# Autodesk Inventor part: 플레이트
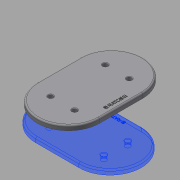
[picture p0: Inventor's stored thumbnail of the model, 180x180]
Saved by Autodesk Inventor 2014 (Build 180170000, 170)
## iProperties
Created: 2016-08
Part Number: 플레이트
Material: 알루미늄 6061
Document SubType Name: Modeling
Designer: mduedu
Density: 2.71 g/cm^3
Appearance: 기본값
Mass: 665.118 g
Surface Area: 557.689 cm^2
Volume: 245.431 cm^3
Author: mduedu
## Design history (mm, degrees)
sketch "스케치1" dims "d0" = 220, "d2" = 130
  geometry: L1 (45, 65)-(-45, 65); L2 (-45, 65)-(-45, -65); L3 (-45, -65)-(45, -65); L4 (45, -65)-(45, 65); L5 (45, 65)-(-45, -65); L6 (-45, 65)-(45, -65); 5 further points
  constraints: 12 end point, 5 midpoint, 2 parallel, 2 vertical alignment, 1 coincident, 1 horizontal, 1 perpendicular, 4 other
extrude "돌출1" new body sketch "스케치1" distance "d3" = 10; taper "d4" = 0 deg
sketch "스케치2"
  geometry: L1 (-57, -25)-(57, -25); L2 (57, -25)-(57, 25); L3 (57, 25)-(-57, 25); L4 (-57, 25)-(-57, -25); L5 (-57, -25)-(57, 25); L6 (57, -25)-(-57, 25); C1 r 5 at (-57, 25); C2 r 5 at (57, 25); C3 r 5 at (57, -25); C4 r 5 at (-57, -25); 1 further point
  constraints: 12 end point, 4 centre point, 4 coincident, 3 equal radius, 2 midpoint, 2 parallel, 1 horizontal, 1 perpendicular
  dimensions: "d5" = 114 distance of L2.end L3.end; "d7" = 50 distance of L1.end L2.end; "d8" = 10 diameter of C1
extrude "돌출2" cut sketch "스케치2" stored distance "d9" = 10; taper "d10" = 0 deg
chamfer "모따기1" distance "d11" = 1; stored, may be unused: second distance "d12" = 2, angle "d13" = 45 deg
fillet "모깎기1" dims "d14" = 3
sketch "스케치3"
  geometry: L1 (-45, -65)-(45, -65) reference; 2 further points
  constraints: 1 vertical alignment, 1 other
  dimensions: "d15" = 12 distance from line of point (0, -53) L1
feature "엠보싱1" sketch "스케치3" dims "d16" = 0.5, "d17" = 0
node "솔리드1"
